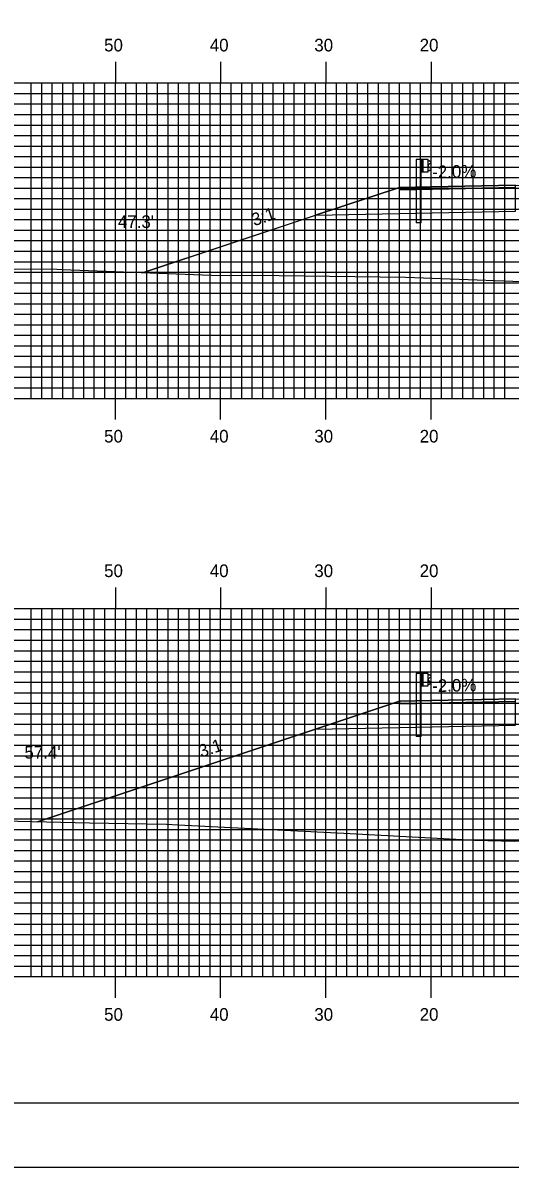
# Model space of a CAD drawing. Extents: x 1813735 to 1814078, y 442591 to 442811.
# Drawn here: x 1813841.7 to 1813888, y 442590.5 to 442699.4 of the extents above; entities that cross this region are included whole.
import ezdxf

# ---------------------------------------------------------------- set-up
doc = ezdxf.new("R2010")
doc.units = 0
for name, color, linetype in [('ANNOTATION', 7, 'Continuous'), ('BORDER', 7, 'Continuous'), ('D_Guardrail_Beam_Lt', 7, 'Continuous'), ('D_Roadway_Centerline', 7, 'Continuous'), ('D_Roadway_Edge_Shoulder', 7, 'Continuous'), ('D_Roadway_SlopeLines', 7, 'Continuous'), ('D_Roadway_SubGrade', 7, 'Continuous'), ('D_Text_Standard', 7, 'Continuous'), ('H_V ANNOTATION', 7, 'Continuous'), ('MAJOR', 7, 'Continuous'), ('MINOR', 7, 'Continuous'), ('PLOT BOUNDARY', 7, 'Continuous'), ('S_Roadway_Centerline', 7, 'Continuous')]:
    doc.layers.add(name, color=color, linetype=linetype)

msp = doc.modelspace()

# ---------------------------------------------------------------- linework, layer by layer
at = {"layer": 'BORDER'}
msp.add_lwpolyline([(1813750.88, 442596.67), (1814070.88, 442596.67), (1814070.88, 442806.67), (1813750.88, 442806.67)], close=True, dxfattribs=at)
at = {"layer": 'D_Guardrail_Beam_Lt'}
for p, q in [((1813879.05, 442686.38), (1813879.05, 442680.38)), ((1813879.52, 442686.38), (1813879.05, 442686.38)), ((1813880.21, 442686.38), (1813879.52, 442686.38)), ((1813879.52, 442686.38), (1813879.52, 442685.22)), ((1813879.59, 442686.38), (1813879.59, 442685.22)), ((1813879.69, 442686.38), (1813879.69, 442685.22)), ((1813880.21, 442685.22), (1813880.21, 442686.38)), ((1813880.21, 442686.3), (1813880.28, 442686.28)), ((1813880.21, 442685.83), (1813880.21, 442685.76)), ((1813880.44, 442686.03), (1813880.25, 442685.9)), ((1813880.3, 442686.28), (1813880.44, 442686.18)), ((1813879.52, 442685.22), (1813880.21, 442685.22)), ((1813879.54, 442680.38), (1813879.54, 442685.22)), ((1813880.28, 442685.31), (1813880.21, 442685.3)), ((1813880.25, 442685.7), (1813880.44, 442685.56)), ((1813880.44, 442685.42), (1813880.3, 442685.32)), ((1813879.54, 442680.38), (1813879.05, 442680.38)), ((1813879.05, 442637.51), (1813879.05, 442631.51)), ((1813879.52, 442637.51), (1813879.05, 442637.51)), ((1813880.21, 442637.51), (1813879.52, 442637.51)), ((1813879.52, 442637.51), (1813879.52, 442636.34)), ((1813879.59, 442637.51), (1813879.59, 442636.34)), ((1813879.69, 442637.51), (1813879.69, 442636.34)), ((1813880.21, 442636.34), (1813880.21, 442637.51)), ((1813880.21, 442637.42), (1813880.28, 442637.41)), ((1813880.21, 442636.96), (1813880.21, 442636.89)), ((1813880.44, 442637.16), (1813880.25, 442637.02)), ((1813880.25, 442636.82), (1813880.44, 442636.69)), ((1813880.3, 442637.4), (1813880.44, 442637.3)), ((1813879.52, 442636.34), (1813880.21, 442636.34)), ((1813879.54, 442631.51), (1813879.54, 442636.34)), ((1813880.28, 442636.44), (1813880.21, 442636.42)), ((1813880.44, 442636.54), (1813880.3, 442636.44)), ((1813879.54, 442631.51), (1813879.05, 442631.51))]:
    msp.add_line(p, q, dxfattribs=at)
for centre, major_axis, start_param, end_param in [((1813880.29, 442685.83), (-0.0789, 0), 5.323254, 6.283185), ((1813880.29, 442685.76), (-0.0789, 0), 6.283185, 7.243116), ((1813880.28, 442686.24), (0.0417, 0), 0.959931, 1.376053), ((1813880.39, 442686.11), (0.0877, 0), 5.323254, 7.243116), ((1813880.28, 442685.35), (0.0417, 0), 4.907132, 5.323254), ((1813880.39, 442685.49), (0.0877, 0), 5.323254, 7.243116), ((1813880.29, 442636.96), (-0.0789, 0), 5.323254, 6.283185), ((1813880.29, 442636.89), (-0.0789, 0), 6.283185, 7.243116), ((1813880.28, 442637.37), (0.0417, 0), 0.959931, 1.376053), ((1813880.39, 442637.23), (0.0877, 0), 5.323254, 7.243116), ((1813880.28, 442636.48), (0.0417, 0), 4.907132, 5.323254), ((1813880.39, 442636.62), (0.0877, 0), 5.323254, 7.243116)]:
    msp.add_ellipse(centre, major_axis=major_axis, ratio=0.995501, start_param=start_param, end_param=end_param, dxfattribs=at)
at = {"layer": 'D_Roadway_Centerline'}
for points in [[(1813853.15, 442675.63), (1813869.5, 442681.08), (1813877.48, 442683.74), (1813880.48, 442683.8), (1813888.48, 442683.96), (1813900.48, 442683.38), (1813912.48, 442682.81), (1813923.3, 442682.29), (1813935.3, 442679.29), (1813935.68, 442679.19), (1813959.63, 442671.18)], [(1813843.09, 442623.4), (1813869.5, 442632.2), (1813877.48, 442634.86), (1813880.48, 442634.92), (1813888.48, 442635.08), (1813900.48, 442634.51), (1813912.48, 442633.93), (1813930.42, 442633.07), (1813942.42, 442630.07), (1813942.8, 442629.98), (1813974.32, 442619.44)]]:
    msp.add_lwpolyline(points, dxfattribs=at)
at = {"layer": 'D_Roadway_Edge_Shoulder'}
for points in [[(1813888.48, 442683.96), (1813880.48, 442683.8), (1813880.48, 442683.8), (1813877.48, 442683.74), (1813877.48, 442683.49), (1813888.48, 442683.71)], [(1813888.48, 442635.08), (1813880.48, 442634.92), (1813880.48, 442634.92), (1813877.48, 442634.86), (1813877.48, 442634.61), (1813888.48, 442634.83)]]:
    msp.add_lwpolyline(points, close=True, dxfattribs=at)
at = {"layer": 'D_Roadway_SlopeLines'}
for points in [[(1813877.48, 442683.74), (1813853.15, 442675.63)], [(1813877.48, 442634.86), (1813843.09, 442623.4)]]:
    msp.add_lwpolyline(points, dxfattribs=at)
at = {"layer": 'D_Roadway_SubGrade'}
for points in [[(1813888.48, 442683.29), (1813888.48, 442683.71), (1813877.48, 442683.49), (1813877.48, 442683.74), (1813869.5, 442681.08), (1813888.48, 442681.46)], [(1813888.48, 442634.42), (1813888.48, 442634.83), (1813877.48, 442634.61), (1813877.48, 442634.86), (1813869.5, 442632.2), (1813888.48, 442632.58)]]:
    msp.add_lwpolyline(points, close=True, dxfattribs=at)
at = {"layer": 'MAJOR'}
for p, q in [((1813850.48, 442695.67), (1813850.48, 442693.67)), ((1813860.48, 442695.67), (1813860.48, 442693.67)), ((1813870.48, 442695.67), (1813870.48, 442693.67)), ((1813880.48, 442695.67), (1813880.48, 442693.67)), ((1813760.48, 442693.67), (1814040.48, 442693.67)), ((1813760.48, 442693.67), (1814040.48, 442693.67)), ((1813850.48, 442663.67), (1813850.48, 442693.67)), ((1813860.48, 442663.67), (1813860.48, 442693.67)), ((1813870.48, 442663.67), (1813870.48, 442693.67)), ((1813880.48, 442663.67), (1813880.48, 442693.67)), ((1813760.48, 442688.67), (1814040.48, 442688.67)), ((1813760.48, 442683.67), (1814040.48, 442683.67)), ((1813760.48, 442678.67), (1814040.48, 442678.67)), ((1813760.48, 442673.67), (1814040.48, 442673.67)), ((1813760.48, 442668.67), (1814040.48, 442668.67)), ((1813760.48, 442663.67), (1814040.48, 442663.67)), ((1813760.48, 442663.67), (1814040.48, 442663.67)), ((1813850.48, 442661.66), (1813850.48, 442663.67)), ((1813860.48, 442661.66), (1813860.48, 442663.67)), ((1813870.48, 442661.66), (1813870.48, 442663.67)), ((1813880.48, 442661.66), (1813880.48, 442663.67)), ((1813850.48, 442645.67), (1813850.48, 442643.67)), ((1813860.48, 442645.67), (1813860.48, 442643.67)), ((1813870.48, 442645.67), (1813870.48, 442643.67)), ((1813880.48, 442645.67), (1813880.48, 442643.67)), ((1813760.48, 442643.67), (1814040.48, 442643.67)), ((1813760.48, 442643.67), (1814040.48, 442643.67)), ((1813850.48, 442608.67), (1813850.48, 442643.67)), ((1813860.48, 442608.67), (1813860.48, 442643.67)), ((1813870.48, 442608.67), (1813870.48, 442643.67)), ((1813880.48, 442608.67), (1813880.48, 442643.67)), ((1813760.48, 442638.67), (1814040.48, 442638.67)), ((1813760.48, 442633.67), (1814040.48, 442633.67)), ((1813760.48, 442628.67), (1814040.48, 442628.67)), ((1813760.48, 442623.67), (1814040.48, 442623.67)), ((1813760.48, 442618.67), (1814040.48, 442618.67)), ((1813760.48, 442613.67), (1814040.48, 442613.67)), ((1813760.48, 442608.67), (1814040.48, 442608.67)), ((1813760.48, 442608.67), (1814040.48, 442608.67)), ((1813850.48, 442606.66), (1813850.48, 442608.67)), ((1813860.48, 442606.66), (1813860.48, 442608.67)), ((1813870.48, 442606.66), (1813870.48, 442608.67)), ((1813880.48, 442606.66), (1813880.48, 442608.67))]:
    msp.add_line(p, q, dxfattribs=at)
at = {"layer": 'MINOR'}
for p, q in [((1813842.48, 442663.67), (1813842.48, 442693.67)), ((1813843.48, 442663.67), (1813843.48, 442693.67)), ((1813844.48, 442663.67), (1813844.48, 442693.67)), ((1813845.48, 442663.67), (1813845.48, 442693.67)), ((1813846.48, 442663.67), (1813846.48, 442693.67)), ((1813847.48, 442663.67), (1813847.48, 442693.67)), ((1813848.48, 442663.67), (1813848.48, 442693.67)), ((1813849.48, 442663.67), (1813849.48, 442693.67)), ((1813851.48, 442663.67), (1813851.48, 442693.67)), ((1813852.48, 442663.67), (1813852.48, 442693.67)), ((1813853.48, 442663.67), (1813853.48, 442693.67)), ((1813854.48, 442663.67), (1813854.48, 442693.67)), ((1813855.48, 442663.67), (1813855.48, 442693.67)), ((1813856.48, 442663.67), (1813856.48, 442693.67)), ((1813857.48, 442663.67), (1813857.48, 442693.67)), ((1813858.48, 442663.67), (1813858.48, 442693.67)), ((1813859.48, 442663.67), (1813859.48, 442693.67)), ((1813861.48, 442663.67), (1813861.48, 442693.67)), ((1813862.48, 442663.67), (1813862.48, 442693.67)), ((1813863.48, 442663.67), (1813863.48, 442693.67)), ((1813864.48, 442663.67), (1813864.48, 442693.67)), ((1813865.48, 442663.67), (1813865.48, 442693.67)), ((1813866.48, 442663.67), (1813866.48, 442693.67)), ((1813867.48, 442663.67), (1813867.48, 442693.67)), ((1813868.48, 442663.67), (1813868.48, 442693.67)), ((1813869.48, 442663.67), (1813869.48, 442693.67)), ((1813871.48, 442663.67), (1813871.48, 442693.67)), ((1813872.48, 442663.67), (1813872.48, 442693.67)), ((1813873.48, 442663.67), (1813873.48, 442693.67)), ((1813874.48, 442663.67), (1813874.48, 442693.67)), ((1813875.48, 442663.67), (1813875.48, 442693.67)), ((1813876.48, 442663.67), (1813876.48, 442693.67)), ((1813877.48, 442663.67), (1813877.48, 442693.67)), ((1813878.48, 442663.67), (1813878.48, 442693.67)), ((1813879.48, 442663.67), (1813879.48, 442693.67)), ((1813881.48, 442663.67), (1813881.48, 442693.67)), ((1813882.48, 442663.67), (1813882.48, 442693.67)), ((1813883.48, 442663.67), (1813883.48, 442693.67)), ((1813884.48, 442663.67), (1813884.48, 442693.67)), ((1813885.48, 442663.67), (1813885.48, 442693.67)), ((1813886.48, 442663.67), (1813886.48, 442693.67)), ((1813887.48, 442663.67), (1813887.48, 442693.67)), ((1813760.48, 442692.67), (1814040.48, 442692.67)), ((1813760.48, 442691.67), (1814040.48, 442691.67)), ((1813760.48, 442690.67), (1814040.48, 442690.67)), ((1813760.48, 442689.67), (1814040.48, 442689.67)), ((1813760.48, 442687.67), (1814040.48, 442687.67)), ((1813760.48, 442686.67), (1814040.48, 442686.67)), ((1813760.48, 442685.67), (1814040.48, 442685.67)), ((1813760.48, 442684.67), (1814040.48, 442684.67)), ((1813760.48, 442682.67), (1814040.48, 442682.67)), ((1813760.48, 442681.67), (1814040.48, 442681.67)), ((1813760.48, 442680.67), (1814040.48, 442680.67)), ((1813760.48, 442679.67), (1814040.48, 442679.67)), ((1813760.48, 442677.67), (1814040.48, 442677.67)), ((1813760.48, 442676.67), (1814040.48, 442676.67)), ((1813760.48, 442675.67), (1814040.48, 442675.67)), ((1813760.48, 442674.67), (1814040.48, 442674.67)), ((1813760.48, 442672.67), (1814040.48, 442672.67)), ((1813760.48, 442671.67), (1814040.48, 442671.67)), ((1813760.48, 442670.67), (1814040.48, 442670.67)), ((1813760.48, 442669.67), (1814040.48, 442669.67)), ((1813760.48, 442667.67), (1814040.48, 442667.67)), ((1813760.48, 442666.67), (1814040.48, 442666.67)), ((1813760.48, 442665.67), (1814040.48, 442665.67)), ((1813760.48, 442664.67), (1814040.48, 442664.67)), ((1813842.48, 442608.67), (1813842.48, 442643.67)), ((1813843.48, 442608.67), (1813843.48, 442643.67)), ((1813844.48, 442608.67), (1813844.48, 442643.67)), ((1813845.48, 442608.67), (1813845.48, 442643.67)), ((1813846.48, 442608.67), (1813846.48, 442643.67)), ((1813847.48, 442608.67), (1813847.48, 442643.67)), ((1813848.48, 442608.67), (1813848.48, 442643.67)), ((1813849.48, 442608.67), (1813849.48, 442643.67)), ((1813851.48, 442608.67), (1813851.48, 442643.67)), ((1813852.48, 442608.67), (1813852.48, 442643.67)), ((1813853.48, 442608.67), (1813853.48, 442643.67)), ((1813854.48, 442608.67), (1813854.48, 442643.67)), ((1813855.48, 442608.67), (1813855.48, 442643.67)), ((1813856.48, 442608.67), (1813856.48, 442643.67)), ((1813857.48, 442608.67), (1813857.48, 442643.67)), ((1813858.48, 442608.67), (1813858.48, 442643.67)), ((1813859.48, 442608.67), (1813859.48, 442643.67)), ((1813861.48, 442608.67), (1813861.48, 442643.67)), ((1813862.48, 442608.67), (1813862.48, 442643.67)), ((1813863.48, 442608.67), (1813863.48, 442643.67)), ((1813864.48, 442608.67), (1813864.48, 442643.67)), ((1813865.48, 442608.67), (1813865.48, 442643.67)), ((1813866.48, 442608.67), (1813866.48, 442643.67)), ((1813867.48, 442608.67), (1813867.48, 442643.67)), ((1813868.48, 442608.67), (1813868.48, 442643.67)), ((1813869.48, 442608.67), (1813869.48, 442643.67)), ((1813871.48, 442608.67), (1813871.48, 442643.67)), ((1813872.48, 442608.67), (1813872.48, 442643.67)), ((1813873.48, 442608.67), (1813873.48, 442643.67)), ((1813874.48, 442608.67), (1813874.48, 442643.67)), ((1813875.48, 442608.67), (1813875.48, 442643.67)), ((1813876.48, 442608.67), (1813876.48, 442643.67)), ((1813877.48, 442608.67), (1813877.48, 442643.67)), ((1813878.48, 442608.67), (1813878.48, 442643.67)), ((1813879.48, 442608.67), (1813879.48, 442643.67)), ((1813881.48, 442608.67), (1813881.48, 442643.67)), ((1813882.48, 442608.67), (1813882.48, 442643.67)), ((1813883.48, 442608.67), (1813883.48, 442643.67)), ((1813884.48, 442608.67), (1813884.48, 442643.67)), ((1813885.48, 442608.67), (1813885.48, 442643.67)), ((1813886.48, 442608.67), (1813886.48, 442643.67)), ((1813887.48, 442608.67), (1813887.48, 442643.67)), ((1813760.48, 442642.67), (1814040.48, 442642.67)), ((1813760.48, 442641.67), (1814040.48, 442641.67)), ((1813760.48, 442640.67), (1814040.48, 442640.67)), ((1813760.48, 442639.67), (1814040.48, 442639.67)), ((1813760.48, 442637.67), (1814040.48, 442637.67)), ((1813760.48, 442636.67), (1814040.48, 442636.67)), ((1813760.48, 442635.67), (1814040.48, 442635.67)), ((1813760.48, 442634.67), (1814040.48, 442634.67)), ((1813760.48, 442632.67), (1814040.48, 442632.67)), ((1813760.48, 442631.67), (1814040.48, 442631.67)), ((1813760.48, 442630.67), (1814040.48, 442630.67)), ((1813760.48, 442629.67), (1814040.48, 442629.67)), ((1813760.48, 442627.67), (1814040.48, 442627.67)), ((1813760.48, 442626.67), (1814040.48, 442626.67)), ((1813760.48, 442625.67), (1814040.48, 442625.67)), ((1813760.48, 442624.67), (1814040.48, 442624.67)), ((1813760.48, 442622.67), (1814040.48, 442622.67)), ((1813760.48, 442621.67), (1814040.48, 442621.67)), ((1813760.48, 442620.67), (1814040.48, 442620.67)), ((1813760.48, 442619.67), (1814040.48, 442619.67)), ((1813760.48, 442617.67), (1814040.48, 442617.67)), ((1813760.48, 442616.67), (1814040.48, 442616.67)), ((1813760.48, 442615.67), (1814040.48, 442615.67)), ((1813760.48, 442614.67), (1814040.48, 442614.67)), ((1813760.48, 442612.67), (1814040.48, 442612.67)), ((1813760.48, 442611.67), (1814040.48, 442611.67)), ((1813760.48, 442610.67), (1814040.48, 442610.67)), ((1813760.48, 442609.67), (1814040.48, 442609.67))]:
    msp.add_line(p, q, dxfattribs=at)
at = {"layer": 'PLOT BOUNDARY'}
msp.add_lwpolyline([(1813734.69, 442590.55), (1814074.69, 442590.55), (1814074.69, 442810.55), (1813734.69, 442810.55)], close=True, dxfattribs=at)
at = {"layer": 'S_Roadway_Centerline'}
for points in [[(1813834.67, 442675.97), (1813844.5, 442675.98), (1813844.92, 442675.96), (1813845.43, 442675.93), (1813860.42, 442675.35), (1813863.63, 442675.39), (1813878.03, 442675.19), (1813888.23, 442674.83), (1813893.46, 442674.58), (1813899.62, 442674.15), (1813910.64, 442673.68), (1813917.16, 442672.69), (1813927.08, 442672.25), (1813934.21, 442672.29), (1813944.58, 442671.29), (1813948.45, 442671.15), (1813959.72, 442671.18), (1813974.92, 442669.72)], [(1813839.85, 442623.47), (1813848.02, 442623.3), (1813855.34, 442623.18), (1813856.46, 442623.11), (1813872.2, 442622.32), (1813884.61, 442621.63), (1813888.42, 442621.55), (1813901.19, 442622.07), (1813903.89, 442621.93), (1813910.4, 442621.94), (1813920.82, 442621.67), (1813930.16, 442620.83), (1813936.94, 442620.46), (1813949.64, 442620.18), (1813953.87, 442620.02), (1813957, 442620), (1813979.82, 442619.26)]]:
    msp.add_lwpolyline(points, dxfattribs=at)

# ---------------------------------------------------------------- texts
at = {"layer": 'ANNOTATION'}
for s, rotation, p in [('-2.0%', 1.1458, (1813880.59, 442684.6)), ('3:1', 18.4349, (1813863.66, 442680.04)), ('-2.0%', 1.1458, (1813880.59, 442635.73)), ('3:1', 18.4348, (1813858.63, 442629.49))]:
    msp.add_text(s, height=1.2, rotation=rotation, dxfattribs=at).set_placement(p)
at = {"layer": 'D_Text_Standard'}
for s, p in [("47.3'", (1813850.72, 442679.88)), ("57.4'", (1813841.84, 442629.4))]:
    msp.add_text(s, height=1.2, dxfattribs=at).set_placement(p)
at = {"layer": 'H_V ANNOTATION'}
for s, p in [('50', (1813849.41, 442696.67)), ('40', (1813859.45, 442696.67)), ('30', (1813869.38, 442696.67)), ('20', (1813879.39, 442696.67)), ('50', (1813849.41, 442659.47)), ('40', (1813859.45, 442659.47)), ('30', (1813869.38, 442659.47)), ('20', (1813879.39, 442659.47)), ('50', (1813849.41, 442646.67)), ('40', (1813859.45, 442646.67)), ('30', (1813869.38, 442646.67)), ('20', (1813879.39, 442646.67)), ('50', (1813849.41, 442604.47)), ('40', (1813859.45, 442604.47)), ('30', (1813869.38, 442604.47)), ('20', (1813879.39, 442604.47))]:
    msp.add_text(s, height=1.2, dxfattribs=at).set_placement(p)

doc.saveas('drawing.dxf')
